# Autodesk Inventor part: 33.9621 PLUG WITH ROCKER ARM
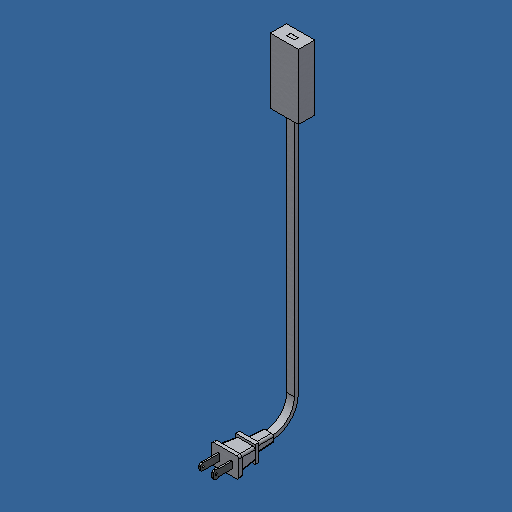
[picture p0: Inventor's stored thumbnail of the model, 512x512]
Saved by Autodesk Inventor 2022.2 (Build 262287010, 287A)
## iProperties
Created: 2018-05
Part Number: 33.9621 PLUG WITH ROCKER ARM
Material: Generic
Document SubType Name: Modeling
Designer: amoles
Density: 1 g/cm^3
Appearance: White
Author: amoles
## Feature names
1. Extrusion1
2. Extrusion2
3. Extrusion3
4. Fillet1
5. Extrusion4
6. Fillet2
7. Extrusion5
8. Extrusion6
9. Extrusion7
10. Fillet3
11. Extrusion8
12. Sweep1
13. Extrusion9
14. Extrusion10
15. Extrusion11
16. Fillet4
17. Fillet5
18. Extrusion12
## Parameters: d0 = 25 mm, d1 = 18.5 mm, d2 = 3.15 mm, d3 = 0, d4 = 1.46 mm, d5 = 6.3 mm, d6 = 1.46 mm, d7 = 6.3 mm, d8 = 12 mm, d9 = 6 mm, d10 = 17.44 mm, d11 = 0, d12 = 8 mm, d13 = 1.46 mm, d14 = 0, d15 = 2 mm, d16 = 1 mm, d17 = 0, d18 = 2 mm, d19 = 2.2 mm, d20 = 15.6 mm, d21 = -5 deg, d22 = 15.8 mm, d23 = 11.37035 mm, d24 = 2.21482 mm, d25 = 3.54 mm, d26 = 0, d27 = 8.5 mm, d28 = 11.5 mm, d29 = 17.33 mm, d30 = -2 deg, d31 = 2 mm, d32 = 3.5 mm, d33 = 7 mm, d34 = 0.1 mm, d35 = 0, d38 = 45 mm, d39 = 0, d40 = 0, d41 = 225.044 mm, d42 = 0, d43 = 15 mm, d44 = 26 mm, d46 = 0, d47 = 75 deg, d49 = 21.5 mm, d50 = 21.5 mm, d51 = 5 mm, d52 = 3 mm, d54 = 12 mm, d55 = 0, d56 = 0.5 mm, d57 = 0.25 mm, d58 = 0.1 mm, d59 = 0, d60 = 33.49218 mm
